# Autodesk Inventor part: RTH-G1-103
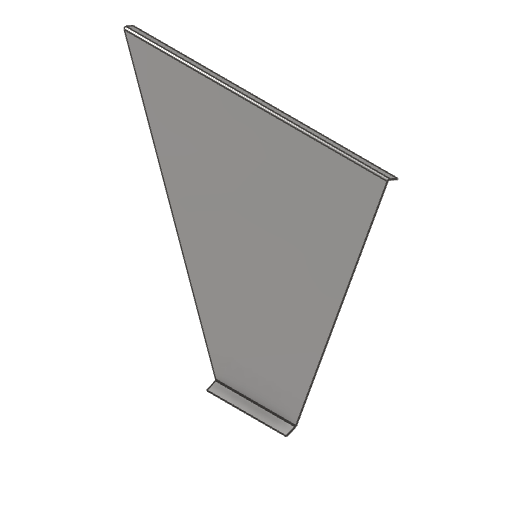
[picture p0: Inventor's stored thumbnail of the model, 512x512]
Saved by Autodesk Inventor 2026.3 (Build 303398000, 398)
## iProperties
Created: 2026-09
Part Number: RTH-G1-103
Material: Steel, Mild
Document SubType Name: Sheet Metal
Designer: mykol
Density: 7.85 g/cm^3
Sheet Metal Rule: Default_mm
Appearance: Semi-Polished
Project: RTH-G1
Description: PANEL X- 3 CS FORMED FLANGES
Stock Number: PL 3 x 1000 x 1060
Mass: 16058.3 g
Surface Area: 13743.4 cm^2
Volume: 2045.64 cm^3
Flat Pattern Width: 96.4808 cm
Flat Pattern Length: 120.911 cm
Flat Pattern Area: 11665.6 cm^2
Sheet Metal Width: 964.808 mm
Sheet Metal Length: 1209.106 mm
Sheet Metal Area: 1166555.328 mm^2
RuthenClass: Fabricated
Thickness: 3
RuthenConfigId: RTH-G1-A-b1a1fe2e
RuthenRuleSet: 1.0.0
RuthenAddInVersion: 1.0.0
Author: mykol
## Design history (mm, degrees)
node "Face1"
  sketch "Sketch1"
    geometry: L1 (-150, 0)-(150, 0); L2 (150, 0)-(500, 984.886); L3 (500, 984.886)-(-500, 984.886); L4 (-500, 984.886)-(-150, 0)
    constraints: 8 end point
node "Flange1"
node "Flange2"
body "Solid1"
face "Plate1" dims "d0" = 3 (= Thickness)
sketch "Sketch2"
  geometry: L1 through (500, 0) direction (-1, 0); L2 through (0, -20) direction (0, -1); L3 (0, -40)-(1000, -40); L4 (1000, -40)-(1000, 0)
  constraints: 6 end point, 1 horizontal, 1 perpendicular, 1 vertical
face "Plate2" dims "d0" = 3 (= Thickness), "d1" = 3 (= Thickness), "d2" = 1.5 (= 0.5 x Thickness), "d3" = 6 (= 2 x Thickness), "d4" = 3 (= Thickness), "d5" = 40, "d6" = 19.89021, "d7" = 3 (= Thickness), "d8" = 12 (= 4 x Thickness), "d9" = 0.5, "d10" = 3 (= JacobiRadiusSize), "SeamGap" = 0.01
bend "Bend1" dims "d0" = 3 (= Thickness), "d1" = 3 (= Thickness), "d2" = 1.5 (= 0.5 x Thickness), "d3" = 6 (= 2 x Thickness), "d4" = 3 (= Thickness), "d5" = 40, "d6" = 19.89021, "d7" = 3 (= Thickness), "SeamGap" = 0.01
feature "Corner1" dims "d5" = 40, "d6" = 19.89021, "d8" = 12 (= 4 x Thickness), "d9" = 0.5, "d10" = 3 (= JacobiRadiusSize)
sketch "Sketch3"
  geometry: L1 through (-150, 0) direction (1, 0); L2 through (0, 20) direction (0, 1); L3 (0, 40)-(-300, 40); L4 (-300, 40)-(-300, 0)
  constraints: 6 end point, 1 horizontal, 1 perpendicular, 1 vertical
face "Plate3" dims "d0" = 3 (= Thickness), "d11" = 3 (= Thickness), "d12" = 1.5 (= 0.5 x Thickness), "d13" = 6 (= 2 x Thickness), "d14" = 3 (= Thickness), "d15" = 40, "d16" = 11.52572, "d17" = 3 (= Thickness), "d18" = 12 (= 4 x Thickness), "d19" = 0.5, "d20" = 3 (= JacobiRadiusSize), "SeamGap" = 0.01
bend "Bend2" dims "d0" = 3 (= Thickness), "d11" = 3 (= Thickness), "d12" = 1.5 (= 0.5 x Thickness), "d13" = 6 (= 2 x Thickness), "d14" = 3 (= Thickness), "d15" = 40, "d16" = 11.52572, "d17" = 3 (= Thickness), "SeamGap" = 0.01
feature "Corner2" dims "d15" = 40, "d16" = 11.52572, "d18" = 12 (= 4 x Thickness), "d19" = 0.5, "d20" = 3 (= JacobiRadiusSize)
feature "Definition1"
other parameters: "Thickness" = 3, "BendRadius" = 3 (= Thickness), "BendReliefWidth" = 3 (= Thickness), "BendReliefDepth" = 1.5 (= 0.5 x Thickness), "CornerReliefSize" = 12 (= 4 x Thickness), "MinimumRemnant" = 6 (= 2 x Thickness), "TransitionRadius" = 3 (= BendRadius), "JacobiRadiusSize" = 3 (= BendRadius), "GapSize" = 3 (= Thickness), "BendRadius" = 3, "BendReliefDepth" = 1.5, "BendReliefWidth" = 3, "CornerReliefSize" = 12, "GapSize" = 3, "JacobiRadiusSize" = 3, "MinimumRemnant" = 6, "Thickness" = 3, "TransitionRadius" = 3
